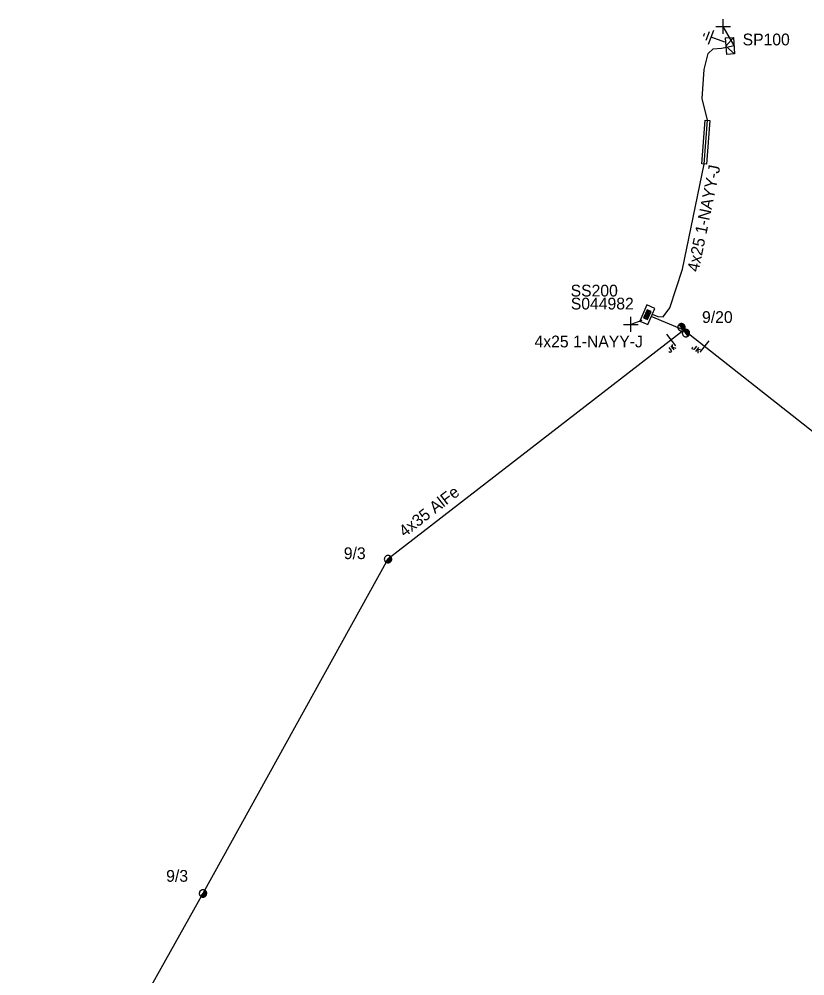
# Model space of a CAD drawing. Extents: x -717562 to -713845, y -1151196 to -1143903.
# Drawn here: x -717164.3 to -717097.5, y -1144017.1 to -1143935.7 of the extents above; entities that cross this region are included whole.
import ezdxf

# ---------------------------------------------------------------- set-up
doc = ezdxf.new("R2010")
doc.units = 0
for name, color, linetype in [('Vrstva 1', 7, 'Continuous'), ('Vrstva 12', 7, 'Continuous'), ('Vrstva 13', 7, 'Continuous'), ('Vrstva 14', 7, 'Continuous'), ('Vrstva 15', 7, 'Continuous'), ('Vrstva 18', 7, 'Continuous'), ('Vrstva 2', 7, 'Continuous'), ('Vrstva 20', 7, 'Continuous'), ('Vrstva 28', 7, 'Continuous'), ('Vrstva 29', 7, 'Continuous'), ('Vrstva 30', 7, 'Continuous'), ('Vrstva 31', 7, 'Continuous'), ('Vrstva 33', 7, 'Continuous'), ('Vrstva 34', 7, 'Continuous'), ('Vrstva 5', 7, 'Continuous'), ('Vrstva 59', 7, 'Continuous'), ('Vrstva 6', 7, 'Continuous'), ('Vrstva 8', 7, 'Continuous'), ('Vrstva 9', 7, 'Continuous')]:
    doc.layers.add(name, color=color, linetype=linetype)

# ---------------------------------------------------------------- blocks, each defined once
blk = doc.blocks.new('NN440')
at = {"layer": 'Vrstva 2'}
for points in [[(0.63, 0), (0.63, 0.06), (0.62, 0.13), (0.6, 0.19), (0.58, 0.25), (0.55, 0.31), (0.51, 0.37), (0.47, 0.42), (0.42, 0.46), (0.37, 0.51), (0.32, 0.54), (0.26, 0.57), (0.2, 0.59), (0.13, 0.61), (0.07, 0.62), (0, 0.63), (-0.06, 0.62), (-0.13, 0.61), (-0.19, 0.59), (-0.26, 0.57), (-0.31, 0.54), (-0.37, 0.51), (-0.42, 0.46), (-0.47, 0.42), (-0.51, 0.37), (-0.54, 0.31), (-0.57, 0.25), (-0.6, 0.19), (-0.62, 0.13), (-0.63, 0.06), (-0.63, 0), (-0.63, -0.07), (-0.62, -0.14), (-0.6, -0.2), (-0.57, -0.26), (-0.54, -0.32), (-0.51, -0.37), (-0.47, -0.43), (-0.42, -0.47), (-0.37, -0.51), (-0.31, -0.55), (-0.26, -0.58), (-0.19, -0.6), (-0.13, -0.62), (-0.06, -0.63), (0, -0.63), (0.07, -0.63), (0.13, -0.62), (0.2, -0.6), (0.26, -0.58), (0.32, -0.55), (0.37, -0.51), (0.42, -0.47), (0.47, -0.43), (0.51, -0.37), (0.55, -0.32), (0.58, -0.26), (0.6, -0.2), (0.62, -0.14), (0.63, -0.07), (0.63, 0)], [(-0.63, 0), (0.63, 0)], [(-0.6, -0.18), (0.57, -0.18)], [(-0.51, -0.32), (0.5, -0.32)], [(-0.37, -0.47), (0.35, -0.47)]]:
    blk.add_lwpolyline(points, dxfattribs=at)
blk = doc.blocks.new('NN450')
at = {"layer": 'Vrstva 2'}
for points in [[(0, 0), (0, 0.07), (-0.01, 0.13), (-0.03, 0.19), (-0.05, 0.25), (-0.08, 0.31), (-0.12, 0.37), (-0.16, 0.42), (-0.21, 0.46), (-0.26, 0.51), (-0.31, 0.54), (-0.37, 0.57), (-0.43, 0.59), (-0.5, 0.61), (-0.56, 0.62), (-0.63, 0.62), (-0.69, 0.62), (-0.75, 0.61), (-0.82, 0.59), (-0.88, 0.57), (-0.94, 0.54), (-0.99, 0.51), (-1.04, 0.46), (-1.09, 0.42), (-1.13, 0.37), (-1.17, 0.31), (-1.2, 0.25), (-1.22, 0.19), (-1.24, 0.13), (-1.25, 0.07), (-1.25, 0), (-1.25, -0.07), (-1.24, -0.13), (-1.22, -0.19), (-1.2, -0.25), (-1.17, -0.31), (-1.13, -0.37), (-1.09, -0.42), (-1.04, -0.46), (-0.99, -0.51), (-0.94, -0.54), (-0.88, -0.57), (-0.82, -0.59), (-0.75, -0.61), (-0.69, -0.62), (-0.62, -0.63), (-0.56, -0.62), (-0.5, -0.61), (-0.43, -0.59), (-0.37, -0.57), (-0.31, -0.54), (-0.26, -0.51), (-0.21, -0.46), (-0.16, -0.42), (-0.12, -0.37), (-0.08, -0.31), (-0.05, -0.25), (-0.03, -0.19), (-0.01, -0.13), (0, -0.07), (0, 0)], [(1.25, 0), (1.25, 0.07), (1.24, 0.13), (1.22, 0.19), (1.2, 0.25), (1.17, 0.31), (1.13, 0.37), (1.09, 0.42), (1.04, 0.46), (0.99, 0.51), (0.94, 0.54), (0.88, 0.57), (0.82, 0.59), (0.75, 0.61), (0.69, 0.62), (0.62, 0.62), (0.56, 0.62), (0.5, 0.61), (0.43, 0.59), (0.37, 0.57), (0.31, 0.54), (0.26, 0.51), (0.21, 0.46), (0.16, 0.42), (0.12, 0.37), (0.08, 0.31), (0.05, 0.25), (0.03, 0.19), (0.01, 0.13), (0, 0.07), (0, 0), (0, -0.07), (0.01, -0.13), (0.03, -0.19), (0.05, -0.25), (0.08, -0.31), (0.12, -0.37), (0.16, -0.42), (0.21, -0.46), (0.26, -0.51), (0.31, -0.54), (0.37, -0.57), (0.43, -0.59), (0.5, -0.61), (0.56, -0.62), (0.63, -0.63), (0.69, -0.62), (0.75, -0.61), (0.82, -0.59), (0.88, -0.57), (0.94, -0.54), (0.99, -0.51), (1.04, -0.46), (1.09, -0.42), (1.13, -0.37), (1.17, -0.31), (1.2, -0.25), (1.22, -0.19), (1.24, -0.13), (1.25, -0.07), (1.25, 0)], [(-1.25, 0), (1.25, 0)], [(-1.23, -0.16), (-0.02, -0.16)], [(-1.16, -0.32), (-0.09, -0.32)], [(-1.03, -0.47), (-0.22, -0.47)], [(0.02, -0.16), (1.23, -0.16)], [(0.09, -0.32), (1.16, -0.32)], [(0.22, -0.47), (1.03, -0.47)]]:
    blk.add_lwpolyline(points, dxfattribs=at)
blk = doc.blocks.new('NN840')
at = {"layer": 'Vrstva 15'}
for points in [[(0.003, 0.619), (0.003, -0.631)], [(-0.745, -0.71), (-0.745, -0.66)], [(-0.73, -0.764), (-0.745, -0.71)], [(-0.657, -0.798), (-0.73, -0.764)], [(-0.627, -0.798), (-0.657, -0.798)], [(-0.558, -0.764), (-0.627, -0.798)], [(-0.538, -0.71), (-0.558, -0.764)], [(-0.538, -0.385), (-0.538, -0.71)], [(-0.332, -0.385), (-0.332, -0.798)], [(-0.332, -0.641), (-0.125, -0.385)], [(-0.263, -0.557), (-0.091, -0.798)]]:
    blk.add_lwpolyline(points, dxfattribs=at)
blk = doc.blocks.new('NN800')
at = {"layer": 'Vrstva 1'}
for points in [[(-0.442, 0.442), (0.442, -0.442)], [(-0.442, -0.442), (0.442, 0.442)]]:
    blk.add_lwpolyline(points, dxfattribs=at)
blk = doc.blocks.new('NN620')
at = {"layer": 'Vrstva 8'}
for points in [[(0.752, 0.004), (-0.748, 0.004)], [(-0.748, 0.004), (-0.748, -0.746)], [(0.752, -0.746), (0.752, 0.004)], [(-0.748, -0.746), (0.752, -0.746)], [(0.368, -0.18), (-0.376, -0.18)], [(-0.376, -0.18), (-0.376, -0.558)], [(-0.376, -0.558), (0.368, -0.558)], [(0.321, -0.227), (-0.329, -0.227)], [(-0.329, -0.227), (-0.329, -0.51)], [(-0.329, -0.51), (0.321, -0.51)], [(0.274, -0.274), (-0.281, -0.274)], [(-0.281, -0.274), (-0.281, -0.463)], [(-0.281, -0.463), (0.274, -0.463)], [(0.227, -0.321), (-0.234, -0.321)], [(-0.234, -0.321), (-0.234, -0.416)], [(-0.234, -0.416), (0.227, -0.416)], [(-0.193, -0.369), (0.185, -0.369)], [(0.227, -0.416), (0.227, -0.321)], [(0.274, -0.463), (0.274, -0.274)], [(0.321, -0.51), (0.321, -0.227)], [(0.368, -0.558), (0.368, -0.18)]]:
    blk.add_lwpolyline(points, dxfattribs=at)
blk = doc.blocks.new('NN630')
at = {"layer": 'Vrstva 9'}
for points in [[(-0.003, -0.7), (-0.703, 0)], [(-0.703, -0.7), (-0.703, 0), (0.697, 0), (0.697, -0.7)], [(-0.703, -0.7), (0.697, -0.7)], [(-0.003, -0.7), (0.697, 0)]]:
    blk.add_lwpolyline(points, dxfattribs=at)
blk = doc.blocks.new('NN810')
at = {"layer": 'Vrstva 14'}
for points in [[(0.004, -0.64), (0.004, -1.89)], [(0.629, -1.89), (-0.621, -1.89)], [(0.388, -2.2), (-0.399, -2.2)], [(0.004, -2.515), (-0.124, -2.515)], [(0.137, -2.515), (0.004, -2.515)]]:
    blk.add_lwpolyline(points, dxfattribs=at)

msp = doc.modelspace()

# ---------------------------------------------------------------- linework, layer by layer
at = {"layer": 'Vrstva 1'}
for points in [[(-717107.8, -1143962.18), (-717132.957, -1143981.649), (-717148.696, -1144010.079), (-717164.334, -1144037.995)], [(-717066.096, -1144015.629), (-717058.655, -1144000.626), (-717081.33, -1143983), (-717107.8, -1143962.18)]]:
    msp.add_lwpolyline(points, dxfattribs=at)
at = {"layer": 'Vrstva 20'}
msp.add_lwpolyline([(-717105.591, -1143944.344), (-717105.861, -1143948.074), (-717106.259, -1143948.046), (-717105.989, -1143944.316)], close=True, dxfattribs=at)
at = {"layer": 'Vrstva 5'}
for points in [[(-717110.482, -1143960.826), (-717110.005, -1143961.028), (-717109.55, -1143961.04), (-717108.98, -1143960.29), (-717107.91, -1143956.99), (-717106.06, -1143948.06), (-717105.79, -1143944.33), (-717106.22, -1143942.47), (-717106.05, -1143940.01), (-717105.72, -1143938.64), (-717105.29, -1143938.25), (-717104.59, -1143938.19), (-717104.17, -1143938.12), (-717103.52, -1143937.98)], [(-717107.8, -1143962.18), (-717110.56, -1143961.01)]]:
    msp.add_lwpolyline(points, dxfattribs=at)
at = {"layer": 'Vrstva 59'}
for points in [[(-717103.52, -1143937.98), (-717104.451, -1143936.351)], [(-717111.376, -1143961.36), (-717112.291, -1143961.683)]]:
    msp.add_lwpolyline(points, dxfattribs=at)

# ---------------------------------------------------------------- block references
at = {"layer": 'Vrstva 13'}
for name, p, xscale, yscale, rotation in [('NN450', (-717107.8, -1143962.18), 0.5000000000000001, 0.5000000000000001, 127.59624444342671), ('NN440', (-717132.956, -1143981.649), 0.5, 0.5, 49.126105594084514), ('NN440', (-717148.696, -1144010.079), 0.5, 0.5, 49.12610550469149)]:
    msp.add_blockref(name, p, dxfattribs=dict(at, xscale=xscale, yscale=yscale, rotation=rotation))
at = {"layer": 'Vrstva 15', "rotation": -110.46854640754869}
msp.add_blockref('NN810', (-717103.69, -1143937.917), dxfattribs=at)
at = {"layer": 'Vrstva 18'}
for p, rotation in [((-717108.878, -1143963.014), 37.73660362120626), ((-717106.042, -1143963.563), -38.43712041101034)]:
    msp.add_blockref('NN840', p, dxfattribs=dict(at, rotation=rotation))
at = {"layer": 'Vrstva 28', "rotation": -113.39945004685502}
msp.add_blockref('NN620', (-717110.56, -1143961.01), dxfattribs=at)
at = {"layer": 'Vrstva 31', "rotation": -85.91438323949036}
msp.add_blockref('NN630', (-717103.52, -1143937.98), dxfattribs=at)
at = {"layer": 'Vrstva 34', "rotation": 45}
for p in [(-717104.451, -1143936.351), (-717112.291, -1143961.683)]:
    msp.add_blockref('NN800', p, dxfattribs=at)

# ---------------------------------------------------------------- texts
at = {"layer": 'Vrstva 12'}
for s, p in [('9/20', (-717106.242, -1143961.565)), ('9/3', (-717136.714, -1143981.649)), ('9/3', (-717151.824, -1144009.089))]:
    msp.add_text(s, height=1, dxfattribs=at).set_placement(p)
at = {"layer": 'Vrstva 2'}
msp.add_text('4x35 AlFe', height=1, rotation=37.781, dxfattribs=at).set_placement((-717131.541, -1143979.821))
at = {"layer": 'Vrstva 29'}
msp.add_text('S044982', height=1, dxfattribs=at).set_placement((-717117.405, -1143960.419))
at = {"layer": 'Vrstva 30'}
msp.add_text('SS200', height=1, dxfattribs=at).set_placement((-717117.42, -1143959.314))
at = {"layer": 'Vrstva 33'}
msp.add_text('SP100', height=1, dxfattribs=at).set_placement((-717102.791, -1143937.956))
at = {"layer": 'Vrstva 6'}
msp.add_text('4x25 1-NAYY-J', height=1, rotation=78.296, dxfattribs=at).set_placement((-717106.539, -1143957.274))
msp.add_text('4x25 1-NAYY-J', height=1, dxfattribs=at).set_placement((-717120.491, -1143963.641))

doc.saveas('drawing.dxf')
